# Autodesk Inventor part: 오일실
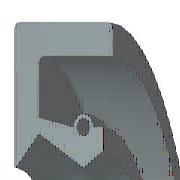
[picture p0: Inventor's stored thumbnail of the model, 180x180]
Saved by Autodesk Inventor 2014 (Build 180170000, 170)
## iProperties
IsCustomPart: 0
Company: 한국ATC센터
Created: 2014-10
Part Number: 오일실
Material: 고무
Description: 오일-실
Document SubType Name: Modeling
Standard: KS B 2804
Designer: KYOUNG IL JANG
Standards Organization: KS
Language: ko-KR
Size Designation: D - 17 32 8
Categories: <MemberInstance><Categories><Category DisplayName="샤프트 부품" InternalName="7f7aeb1f-a693-4053-b835-cee3144e0d98" Mnemonic="SHFT"><Category DisplayName="실링" Intern
Density: 0.93 g/cm^3
Mass: 2.28027 g
Surface Area: 32.1224 cm^2
Volume: 2.45191 cm^3
Appearance: 고무 - 검은색 - 버전 1.1
Author: KYOUNG IL JANG
Revision Number: 1
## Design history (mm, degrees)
revolve "본체" stored, may be unused: angle "d17" = 90 deg
revolve "스프링1" stored, may be unused: angle "d18" = 90 deg
body "Solid1"
sketch "스케치1"
  geometry: L1 (0, 16)-(8, 16); L2 (8, 14.25)-(1.75, 14.25); L3 (1.75, 10.25)-(4.9, 8.5); L4 (4.9, 8.5)-(0, 8.5); L5 (0, 0)-(9.586, 0) reference; L6 (4.9, 8.5)-(6.3, 9.375); L7 (0, 18)-(0, -3) reference; L8 (-1.941, 0)-(11.507, 0) reference; L9 (4.2, 10.6)-(1.75, 11.21); L10 (1.75, 11.21)-(1.75, 14.25); L11 (0, 16)-(0, 8.588); L12 (4.9, 8.5)-(0, 8.5); L13 (1.75, 10.25)-(0.152, 8.528); L14 (8, 16)-(8, 14.25); L15 (5.6, 10.6)-(6.3, 10.6); L16 (6.3, 10.6)-(6.3, 9.375); C1 r 0.455 at (4.9, 10.6); A1 r 0.7 centre (4.9, 10.6) between (5.6, 10.6) and (4.2, 10.6); A2 r 0.088 centre (0.088, 8.588) between (0, 8.588) and (0.152, 8.528); 1 further point
  constraints: 28 end point, 5 horizontal alignment, 5 point on line, 4 point on circle, 4 vertical alignment, 3 centre point, 3 tangent, 2 collinear, 2 horizontal, 2 perpendicular, 1 coincident, 1 parallel
  dimensions: "d0" = 32 diameter of L1 L5 (= SD2); "d1" = 1.75 distance of L1.end L2.start (= SD); "d2" = 0.91 diameter of C1 (= SPDI); "d3" = 1.4 diameter of A1 (= SPDA); "d4" = 17 diameter of L3.end L5 (= NND); "d5" = 20.5 diameter of L3.start L5 (= TKDM); "d7" = 22.42 diameter of L9.end L5 (= TKDM + 0.24 x SWDT); "d8" = 1.75 distance between parallel lines of L11 L10 (= SD); "d9" = 4.9 distance from line of L11 C1.centre (= SPDST); "d10" = 21.2 diameter of C1.centre L5 (= HLDM); "d11" = 0.0875 radius of A2 (= 0.25 x LAB); "d12" = 6.3 distance between parallel lines of L11 L16 (= SDI); "d13" = 18.75 diameter of L6.end L5 (= ABDM); "d14" = 8 distance from line of L11 L1.end (= SWDT)
fillet "모깎기1" dims "d6" = 0.3 (= RR)
other parameters: "SD2" = 32 [user parameter; used in 1 equation term], "SWDT" = 8 [user parameter; used in 2 equation terms], "RR" = 0.3 [user parameter; used in 1 equation term], "SD" = 1.75 [user parameter; used in 2 equation terms], "NND" = 17 [user parameter; used in 1 equation term], "SPDA" = 1.4 [user parameter; used in 1 equation term], "SPDI" = 0.91 [user parameter; used in 1 equation term], "TKDM" = 20.5 [user parameter; used in 2 equation terms], "HLDM" = 21.2 [user parameter; used in 1 equation term], "ABDM" = 18.75 [user parameter; used in 1 equation term], "SDI" = 6.3 [user parameter; used in 1 equation term], "SPDST" = 4.9 [user parameter; used in 1 equation term], "LAB" = 0.35 [user parameter; used in 1 equation term], "d15" = 0, "d16" = 0, "d19" = 0
